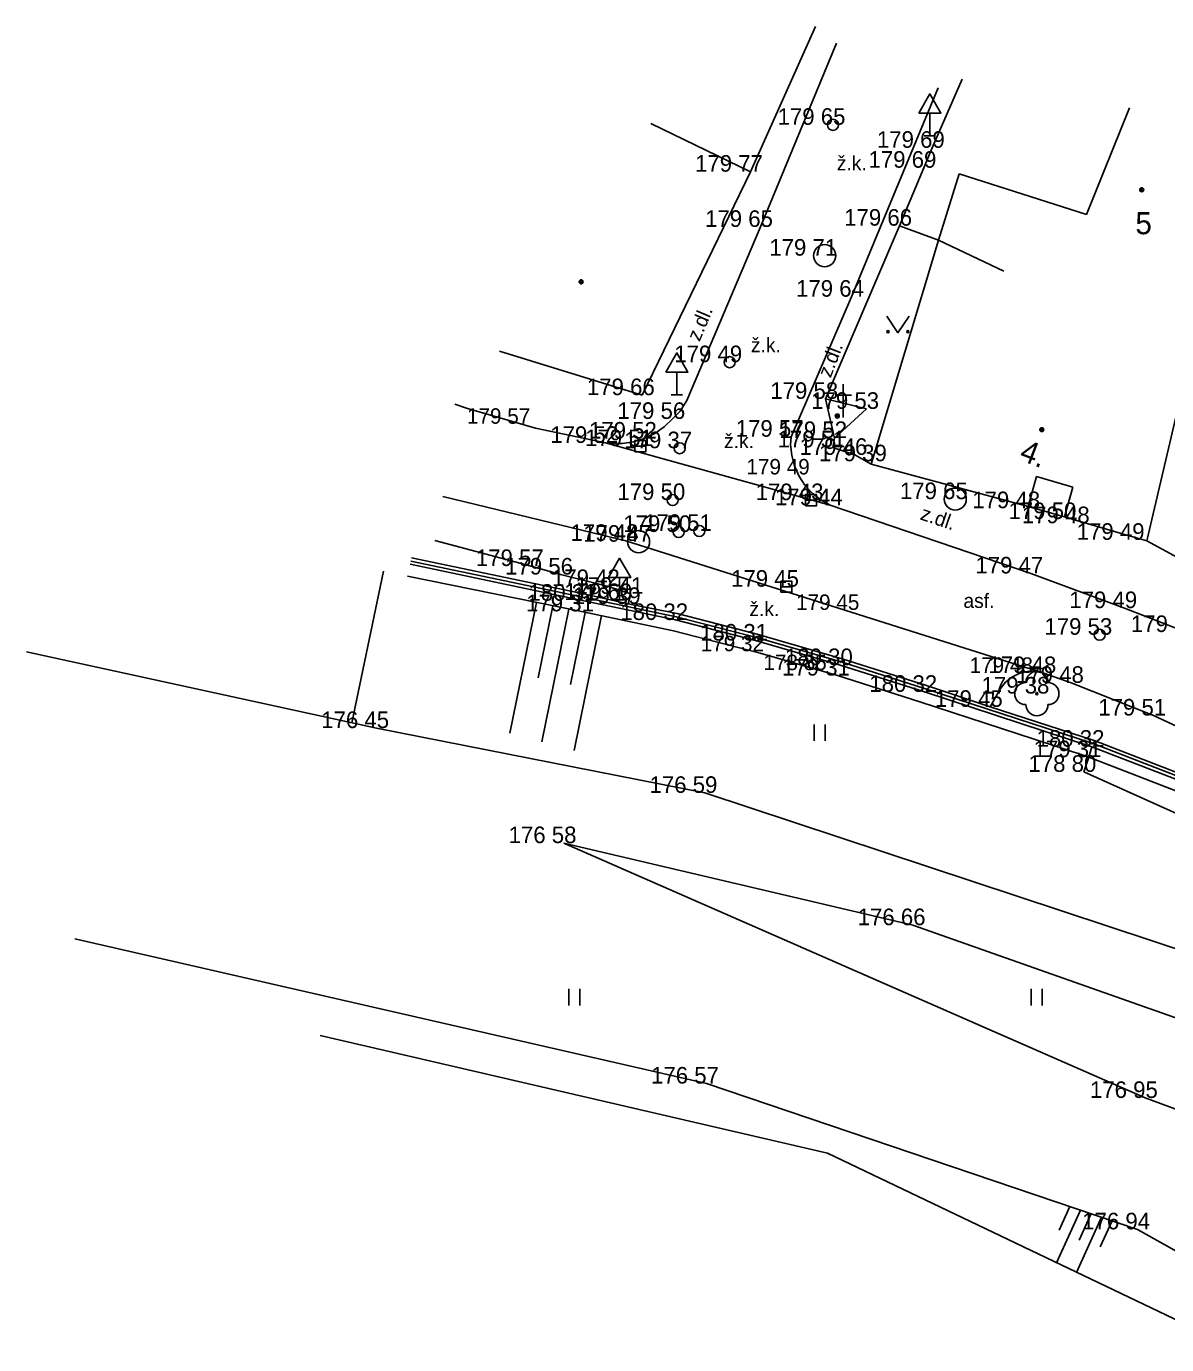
# Model space of a CAD drawing. Extents: x -537755 to -537431, y -1180722 to -1180510.
# Drawn here: x -537754.9 to -537703.4, y -1180569.1 to -1180509.5 of the extents above; entities that cross this region are included whole.
import ezdxf

# ---------------------------------------------------------------- set-up
doc = ezdxf.new("R2010")
doc.units = 0
for name, color, linetype in [('Vrstva 1', 7, 'Continuous'), ('Vrstva 10', 7, 'Continuous'), ('Vrstva 11', 7, 'Continuous'), ('Vrstva 14', 7, 'Continuous'), ('Vrstva 15', 7, 'Continuous'), ('Vrstva 22', 7, 'Continuous'), ('Vrstva 27', 7, 'Continuous'), ('Vrstva 28', 7, 'Continuous'), ('Vrstva 3', 7, 'Continuous'), ('Vrstva 31', 7, 'Continuous'), ('Vrstva 34', 7, 'Continuous'), ('Vrstva 36', 7, 'Continuous'), ('Vrstva 39', 7, 'Continuous'), ('Vrstva 40', 7, 'Continuous'), ('Vrstva 41', 7, 'Continuous'), ('Vrstva 47', 7, 'Continuous'), ('Vrstva 5', 7, 'Continuous'), ('Vrstva 6', 7, 'Continuous'), ('Vrstva 7', 7, 'Continuous'), ('Vrstva 8', 7, 'Continuous'), ('Vrstva 9', 7, 'Continuous')]:
    doc.layers.add(name, color=color, linetype=linetype)

msp = doc.modelspace()

# ---------------------------------------------------------------- linework, layer by layer
at = {"layer": 'Vrstva 1'}
for p, q in [((-537718.52, -1180514.03), (-537718.52, -1180514.03)), ((-537718.49, -1180513.98), (-537718.49, -1180513.98)), ((-537718.434, -1180514.114), (-537718.434, -1180514.114)), ((-537714, -1180515.02), (-537714, -1180515.02)), ((-537714.38, -1180515.92), (-537714.38, -1180515.92)), ((-537722.22, -1180516.1), (-537722.22, -1180516.1)), ((-537720.86, -1180516.44), (-537720.86, -1180516.44)), ((-537721.769, -1180518.596), (-537721.769, -1180518.596)), ((-537715.48, -1180518.54), (-537715.48, -1180518.54)), ((-537718.865, -1180519.895), (-537718.865, -1180519.895)), ((-537717.656, -1180521.751), (-537717.656, -1180521.751)), ((-537723.16, -1180524.71), (-537723.16, -1180524.71)), ((-537727.14, -1180526.11), (-537727.14, -1180526.11)), ((-537727.11, -1180526.2), (-537727.11, -1180526.2)), ((-537727.04, -1180526.19), (-537727.04, -1180526.19)), ((-537727.11, -1180526.24), (-537727.11, -1180526.24)), ((-537725.093, -1180526.449), (-537725.093, -1180526.449)), ((-537718.82, -1180526.37), (-537718.82, -1180526.37)), ((-537718.64, -1180526.57), (-537718.64, -1180526.57)), ((-537725.734, -1180527.276), (-537725.734, -1180527.276)), ((-537716.97, -1180526.82), (-537716.97, -1180526.82)), ((-537732.701, -1180527.495), (-537732.701, -1180527.495)), ((-537726.117, -1180527.687), (-537726.117, -1180527.687)), ((-537720.248, -1180527.828), (-537720.248, -1180527.828)), ((-537720.07, -1180527.44), (-537720.07, -1180527.44)), ((-537728.765, -1180528.361), (-537728.765, -1180528.361)), ((-537728.157, -1180528.553), (-537728.157, -1180528.553)), ((-537727.195, -1180528.506), (-537727.195, -1180528.506)), ((-537727.176, -1180528.6), (-537727.176, -1180528.6)), ((-537727.016, -1180528.165), (-537727.016, -1180528.165)), ((-537725.42, -1180528.6), (-537725.42, -1180528.6)), ((-537720.383, -1180528.081), (-537720.383, -1180528.081)), ((-537718.49, -1180528.56), (-537718.49, -1180528.56)), ((-537718.42, -1180528.14), (-537718.42, -1180528.14)), ((-537718.28, -1180528.08), (-537718.28, -1180528.08)), ((-537717.5, -1180528.9), (-537717.5, -1180528.9)), ((-537716.62, -1180529.19), (-537716.62, -1180529.19)), ((-537720.22, -1180529.54), (-537720.22, -1180529.54)), ((-537720.067, -1180529.785), (-537720.067, -1180529.785)), ((-537716.76, -1180529.32), (-537716.76, -1180529.32)), ((-537716.73, -1180529.27), (-537716.73, -1180529.27)), ((-537719.94, -1180529.88), (-537719.94, -1180529.88)), ((-537725.732, -1180530.939), (-537725.732, -1180530.939)), ((-537720.26, -1180530.83), (-537720.26, -1180530.83)), ((-537719.664, -1180530.389), (-537719.664, -1180530.389)), ((-537719.481, -1180530.947), (-537719.481, -1180530.947)), ((-537712.96, -1180530.901), (-537712.96, -1180530.901)), ((-537719.385, -1180530.998), (-537719.385, -1180530.998)), ((-537718.611, -1180531.177), (-537718.611, -1180531.177)), ((-537718.48, -1180531.24), (-537718.48, -1180531.24)), ((-537718.319, -1180531.314), (-537718.319, -1180531.314)), ((-537709.69, -1180531.31), (-537709.69, -1180531.31)), ((-537708.05, -1180531.8), (-537708.05, -1180531.8)), ((-537707.45, -1180531.99), (-537707.45, -1180531.99)), ((-537725.465, -1180532.386), (-537725.465, -1180532.386)), ((-537725.43, -1180532.33), (-537725.43, -1180532.33)), ((-537724.53, -1180532.38), (-537724.53, -1180532.38)), ((-537724.528, -1180532.338), (-537724.528, -1180532.338)), ((-537704.97, -1180532.74), (-537704.97, -1180532.74)), ((-537727.849, -1180532.79), (-537727.849, -1180532.79)), ((-537727.39, -1180532.82), (-537727.39, -1180532.82)), ((-537727.275, -1180532.826), (-537727.275, -1180532.826)), ((-537727.233, -1180532.863), (-537727.233, -1180532.863)), ((-537704.3, -1180532.78), (-537704.3, -1180532.78)), ((-537732.13, -1180533.925), (-537732.13, -1180533.925)), ((-537730.807, -1180534.309), (-537730.807, -1180534.309)), ((-537709.549, -1180534.261), (-537709.549, -1180534.261)), ((-537728.69, -1180534.83), (-537728.69, -1180534.83)), ((-537720.593, -1180534.859), (-537720.593, -1180534.859)), ((-537729.748, -1180535.494), (-537729.748, -1180535.494)), ((-537728.13, -1180535.46), (-537728.13, -1180535.46)), ((-537727.75, -1180535.64), (-537727.75, -1180535.64)), ((-537727.63, -1180535.18), (-537727.63, -1180535.18)), ((-537705.49, -1180535.64), (-537705.49, -1180535.64)), ((-537729.861, -1180535.974), (-537729.861, -1180535.974)), ((-537717.823, -1180535.909), (-537717.823, -1180535.909)), ((-537705.304, -1180535.827), (-537705.304, -1180535.827)), ((-537725.87, -1180536.37), (-537725.87, -1180536.37)), ((-537725.602, -1180536.364), (-537725.602, -1180536.364)), ((-537706.49, -1180536.9), (-537706.49, -1180536.9)), ((-537721.99, -1180537.295), (-537721.99, -1180537.295)), ((-537706.429, -1180537.032), (-537706.429, -1180537.032)), ((-537722.135, -1180537.775), (-537722.135, -1180537.775)), ((-537719.301, -1180538.63), (-537719.301, -1180538.63)), ((-537718.45, -1180538.38), (-537718.45, -1180538.38)), ((-537718.159, -1180538.404), (-537718.159, -1180538.404)), ((-537718.289, -1180538.876), (-537718.289, -1180538.876)), ((-537709.978, -1180538.754), (-537709.978, -1180538.754)), ((-537708.96, -1180538.764), (-537708.96, -1180538.764)), ((-537707.713, -1180539.205), (-537707.713, -1180539.205)), ((-537714.344, -1180539.612), (-537714.344, -1180539.612)), ((-537709.27, -1180539.69), (-537709.27, -1180539.69)), ((-537711.38, -1180540.29), (-537711.38, -1180540.29)), ((-537703.993, -1180540.684), (-537703.993, -1180540.684)), ((-537739.12, -1180541.25), (-537739.12, -1180541.25)), ((-537706.82, -1180542.13), (-537706.82, -1180542.13)), ((-537706.782, -1180542.092), (-537706.782, -1180542.092)), ((-537706.917, -1180542.563), (-537706.917, -1180542.563)), ((-537707.15, -1180543.23), (-537707.15, -1180543.23)), ((-537724.28, -1180544.18), (-537724.28, -1180544.18)), ((-537730.65, -1180546.45), (-537730.65, -1180546.45)), ((-537714.87, -1180550.16), (-537714.87, -1180550.16)), ((-537724.21, -1180557.32), (-537724.21, -1180557.32)), ((-537704.37, -1180557.97), (-537704.37, -1180557.97)), ((-537704.72, -1180563.91), (-537704.72, -1180563.91))]:
    msp.add_line(p, q, dxfattribs=at)
at = {"layer": 'Vrstva 10'}
for p, q in [((-537718.33, -1180510.282), (-537721.769, -1180518.596)), ((-537721.769, -1180518.596), (-537725.093, -1180526.449)), ((-537720.383, -1180528.081), (-537717.656, -1180521.751)), ((-537728.765, -1180528.361), (-537718.611, -1180531.177)), ((-537736.128, -1180530.783), (-537727.849, -1180532.79)), ((-537709.549, -1180534.261), (-537718.611, -1180531.177)), ((-537708.96, -1180538.764), (-537727.849, -1180532.79)), ((-537703.993, -1180540.684), (-537697.619, -1180543.667))]:
    msp.add_line(p, q, dxfattribs=at)
for points in [[(-537716.643, -1180519.316), (-537713.728, -1180512.314)], [(-537717.656, -1180521.751), (-537716.643, -1180519.316)], [(-537728.765, -1180528.361), (-537731.935, -1180527.693), (-537735.048, -1180526.793), (-537735.582, -1180526.613)], [(-537725.093, -1180526.449), (-537725.395, -1180526.93), (-537725.734, -1180527.276)], [(-537725.734, -1180527.276), (-537726.111, -1180527.635), (-537726.538, -1180527.932), (-537727.016, -1180528.165), (-537727.502, -1180528.315), (-537728.017, -1180528.391), (-537728.538, -1180528.388), (-537728.765, -1180528.361)], [(-537718.611, -1180531.177), (-537719.042, -1180530.937), (-537719.429, -1180530.631), (-537719.762, -1180530.266), (-537720.032, -1180529.853), (-537720.231, -1180529.401), (-537720.354, -1180528.923), (-537720.4, -1180528.432), (-537720.383, -1180528.081)], [(-537736.491, -1180532.767), (-537732.13, -1180533.925), (-537730.807, -1180534.309), (-537728.69, -1180534.83)], [(-537702.519, -1180536.908), (-537705.304, -1180535.827), (-537709.549, -1180534.261)], [(-537728.69, -1180534.83), (-537727.63, -1180535.18), (-537727.75, -1180535.64)], [(-537711.38, -1180540.29), (-537710.92, -1180539.462), (-537710.687, -1180539.176), (-537710.398, -1180538.946), (-537710.067, -1180538.783), (-537709.708, -1180538.696), (-537709.339, -1180538.688), (-537708.96, -1180538.764)], [(-537708.96, -1180538.764), (-537707.713, -1180539.205), (-537703.993, -1180540.684)]]:
    msp.add_lwpolyline(points, dxfattribs=at)
at = {"layer": 'Vrstva 11'}
msp.add_line((-537715.48, -1180518.54), (-537718.82, -1180526.37), dxfattribs=at)
msp.add_lwpolyline([(-537718.42, -1180528.14), (-537718.49, -1180528.56), (-537717.5, -1180528.9), (-537716.76, -1180529.32)], dxfattribs=at)
at = {"layer": 'Vrstva 14'}
for p, q in [((-537754.95, -1180537.81), (-537739.12, -1180541.25)), ((-537739.12, -1180541.25), (-537724.28, -1180544.18)), ((-537700.77, -1180546.1), (-537707.15, -1180543.23)), ((-537724.28, -1180544.18), (-537700.48, -1180552.05)), ((-537730.65, -1180546.45), (-537714.87, -1180550.16)), ((-537730.65, -1180546.45), (-537704.37, -1180557.97)), ((-537714.87, -1180550.16), (-537694.25, -1180557.43)), ((-537724.21, -1180557.32), (-537752.76, -1180550.78)), ((-537741.67, -1180555.14), (-537718.74, -1180560.47)), ((-537704.72, -1180563.91), (-537724.21, -1180557.32)), ((-537704.37, -1180557.97), (-537687.94, -1180563.99)), ((-537718.74, -1180560.47), (-537699.95, -1180569.45)), ((-537683.35, -1180575.9), (-537704.72, -1180563.91))]:
    msp.add_line(p, q, dxfattribs=at)
msp.add_lwpolyline([(-537707.15, -1180543.23), (-537706.917, -1180542.563), (-537706.782, -1180542.092)], dxfattribs=at)
at = {"layer": 'Vrstva 15'}
for p, q in [((-537740.233, -1180541.008), (-537738.809, -1180534.154)), ((-537733.094, -1180541.483), (-537731.89, -1180535.57)), ((-537731.82, -1180538.986), (-537731.155, -1180535.719)), ((-537731.643, -1180541.873), (-537730.42, -1180535.869)), ((-537730.35, -1180539.285), (-537729.685, -1180536.019)), ((-537730.192, -1180542.264), (-537728.95, -1180536.168)), ((-537707.295, -1180563.039), (-537708.375, -1180565.423)), ((-537707.773, -1180562.878), (-537708.258, -1180563.952)), ((-537706.345, -1180563.361), (-537707.473, -1180565.855)), ((-537706.82, -1180563.2), (-537707.365, -1180564.403)), ((-537705.868, -1180563.522), (-537706.404, -1180564.706))]:
    msp.add_line(p, q, dxfattribs=at)
at = {"layer": 'Vrstva 22'}
msp.add_circle((-537709.27, -1180539.69), 0.05, dxfattribs=at)
for centre, start, end in [((-537709.27, -1180539.19), 0, 180), ((-537709.77, -1180539.69), 90, 270), ((-537708.77, -1180539.69), 270, 90), ((-537709.27, -1180540.19), 180, 0)]:
    msp.add_arc(centre, 0.5, start, end, dxfattribs=at)
at = {"layer": 'Vrstva 27'}
for p, q in [((-537727.445, -1180528.506), (-537726.945, -1180528.506)), ((-537719.731, -1180530.947), (-537719.231, -1180530.947)), ((-537720.843, -1180534.859), (-537720.343, -1180534.859))]:
    msp.add_line(p, q, dxfattribs=at)
for points in [[(-537727.445, -1180528.756), (-537726.945, -1180528.756), (-537726.945, -1180528.256), (-537727.445, -1180528.256)], [(-537719.731, -1180531.197), (-537719.231, -1180531.197), (-537719.231, -1180530.697), (-537719.731, -1180530.697)], [(-537720.843, -1180535.109), (-537720.343, -1180535.109), (-537720.343, -1180534.609), (-537720.843, -1180534.609)]]:
    msp.add_lwpolyline(points, close=True, dxfattribs=at)
for centre in [(-537718.865, -1180519.895), (-537712.96, -1180530.901), (-537727.275, -1180532.826)]:
    msp.add_circle(centre, 0.5, dxfattribs=at)
at = {"layer": 'Vrstva 28'}
for centre in [(-537718.49, -1180513.98), (-537723.16, -1180524.71), (-537725.732, -1180530.939), (-537725.465, -1180532.386), (-537724.528, -1180532.338), (-537706.429, -1180537.032)]:
    msp.add_circle(centre, 0.25, dxfattribs=at)
at = {"layer": 'Vrstva 31'}
msp.add_circle((-537725.42, -1180528.6), 0.25, dxfattribs=at)
at = {"layer": 'Vrstva 34'}
for p, q in [((-537714.11, -1180513.453), (-537714.11, -1180514.471)), ((-537714.36, -1180514.471), (-537713.86, -1180514.471)), ((-537725.544, -1180525.161), (-537725.544, -1180526.179)), ((-537725.794, -1180526.179), (-537725.294, -1180526.179)), ((-537728.13, -1180534.444), (-537728.13, -1180535.46)), ((-537728.38, -1180535.46), (-537727.88, -1180535.46))]:
    msp.add_line(p, q, dxfattribs=at)
for points in [[(-537714.61, -1180513.453), (-537713.61, -1180513.453), (-537714.11, -1180512.587)], [(-537726.044, -1180525.161), (-537725.044, -1180525.161), (-537725.544, -1180524.295)], [(-537728.63, -1180534.444), (-537727.63, -1180534.444), (-537728.13, -1180533.576)]]:
    msp.add_lwpolyline(points, close=True, dxfattribs=at)
at = {"layer": 'Vrstva 36'}
for p, q in [((-537719.339, -1180541.831), (-537719.339, -1180541.081)), ((-537718.839, -1180541.831), (-537718.839, -1180541.081)), ((-537730.435, -1180553.785), (-537730.435, -1180553.035)), ((-537729.935, -1180553.785), (-537729.935, -1180553.035)), ((-537709.523, -1180553.785), (-537709.523, -1180553.035)), ((-537709.023, -1180553.785), (-537709.023, -1180553.035))]:
    msp.add_line(p, q, dxfattribs=at)
msp.add_lwpolyline([(-537716.05, -1180522.631), (-537715.55, -1180523.381), (-537715.05, -1180522.631)], dxfattribs=at)
for centre in [(-537716, -1180523.331), (-537715.101, -1180523.331)]:
    msp.add_circle(centre, 0.05, dxfattribs=at)
at = {"layer": 'Vrstva 39'}
for centre, radius in [((-537704.531, -1180516.916), 0.09), ((-537704.531, -1180516.916), 0.0398), ((-537729.871, -1180521.078), 0.09), ((-537729.871, -1180521.078), 0.0398), ((-537718.293, -1180527.144), 0.09), ((-537718.293, -1180527.144), 0.0398), ((-537709.049, -1180527.761), 0.09), ((-537709.049, -1180527.761), 0.0398)]:
    msp.add_circle(centre, radius, dxfattribs=at)
at = {"layer": 'Vrstva 41'}
for p, q in [((-537718.395, -1180526.207), (-537717.645, -1180526.207)), ((-537718.02, -1180527.207), (-537718.02, -1180525.707))]:
    msp.add_line(p, q, dxfattribs=at)
at = {"layer": 'Vrstva 5'}
for p, q in [((-537722.22, -1180516.1), (-537719.27, -1180509.53)), ((-537726.72, -1180513.921), (-537722.22, -1180516.1)), ((-537727.11, -1180526.2), (-537722.22, -1180516.1)), ((-537713.72, -1180519.19), (-537712.78, -1180516.19)), ((-537712.78, -1180516.19), (-537707.023, -1180518.032)), ((-537713.72, -1180519.19), (-537716.76, -1180529.32)), ((-537710.766, -1180520.598), (-537713.72, -1180519.19)), ((-537704.3, -1180532.78), (-537701.72, -1180521.76)), ((-537728.09, -1180525.897), (-537733.561, -1180524.209)), ((-537716.97, -1180526.82), (-537718.82, -1180526.37)), ((-537718.82, -1180526.37), (-537718.42, -1180528.14)), ((-537718.42, -1180528.14), (-537716.97, -1180526.82)), ((-537716.76, -1180529.32), (-537709.668, -1180531.229)), ((-537709.668, -1180531.229), (-537709.282, -1180529.883)), ((-537709.282, -1180529.883), (-537707.637, -1180530.354)), ((-537707.637, -1180530.354), (-537708.022, -1180531.7)), ((-537709.668, -1180531.229), (-537708.022, -1180531.7)), ((-537708.022, -1180531.7), (-537707.42, -1180531.883)), ((-537704.932, -1180532.605), (-537704.3, -1180532.78)), ((-537694.81, -1180537.96), (-537704.3, -1180532.78))]:
    msp.add_line(p, q, dxfattribs=at)
for points in [[(-537707.023, -1180518.032), (-537705.076, -1180513.21)], [(-537727.11, -1180526.2), (-537728.09, -1180525.897)]]:
    msp.add_lwpolyline(points, dxfattribs=at)
at = {"layer": 'Vrstva 6'}
msp.add_line((-537707.42, -1180531.883), (-537704.932, -1180532.605), dxfattribs=at)
at = {"layer": 'Vrstva 7'}
for p, q in [((-537714, -1180515.02), (-537712.64, -1180511.91)), ((-537715.48, -1180518.54), (-537714.38, -1180515.92)), ((-537713.72, -1180519.19), (-537715.48, -1180518.54)), ((-537729.748, -1180535.494), (-537737.605, -1180533.848)), ((-537729.686, -1180535.2), (-537737.543, -1180533.554)), ((-537729.861, -1180535.974), (-537737.718, -1180534.383)), ((-537706.782, -1180542.092), (-537714.344, -1180539.612)), ((-537707.182, -1180542.476), (-537714.563, -1180540.056)), ((-537699.762, -1180544.81), (-537706.782, -1180542.092)), ((-537699.647, -1180544.533), (-537706.681, -1180541.809)), ((-537706.917, -1180542.563), (-537707.182, -1180542.476)), ((-537699.969, -1180545.27), (-537706.917, -1180542.563))]:
    msp.add_line(p, q, dxfattribs=at)
for points in [[(-537721.99, -1180537.295), (-537725.602, -1180536.364), (-537729.748, -1180535.494)], [(-537727.75, -1180535.64), (-537729.686, -1180535.2)], [(-537721.911, -1180537.006), (-537725.534, -1180536.072), (-537727.75, -1180535.64)], [(-537721.773, -1180537.868), (-537725.7, -1180536.856), (-537729.861, -1180535.974)], [(-537714.344, -1180539.612), (-537718.159, -1180538.404), (-537721.99, -1180537.295)], [(-537714.252, -1180539.326), (-537718.072, -1180538.117), (-537721.911, -1180537.006)], [(-537714.563, -1180540.056), (-537718.289, -1180538.876), (-537721.773, -1180537.868)], [(-537706.681, -1180541.809), (-537711.38, -1180540.29), (-537714.252, -1180539.326)]]:
    msp.add_lwpolyline(points, dxfattribs=at)
at = {"layer": 'Vrstva 8'}
msp.add_line((-537714, -1180515.02), (-537714.38, -1180515.92), dxfattribs=at)
at = {"layer": 'Vrstva 9'}
for p, q in [((-537729.717, -1180535.347), (-537737.574, -1180533.701)), ((-537706.732, -1180541.951), (-537714.298, -1180539.469)), ((-537699.704, -1180544.671), (-537706.732, -1180541.951))]:
    msp.add_line(p, q, dxfattribs=at)
for points in [[(-537721.95, -1180537.15), (-537725.568, -1180536.218), (-537729.717, -1180535.347)], [(-537714.298, -1180539.469), (-537718.115, -1180538.26), (-537721.95, -1180537.15)]]:
    msp.add_lwpolyline(points, dxfattribs=at)

# ---------------------------------------------------------------- texts
at = {"layer": 'Vrstva 3'}
for s, height, p in [('179 65 ', 0.75, (-537720.99, -1180513.98)), ('179 69 ', 0.75, (-537716.5, -1180515.02)), ('179 77 ', 0.75, (-537724.72, -1180516.1)), ('179 69 ', 0.75, (-537716.88, -1180515.92)), ('179 65 ', 0.75, (-537724.269, -1180518.596)), ('179 66 ', 0.75, (-537717.98, -1180518.54)), ('179 71 ', 0.75, (-537721.365, -1180519.895)), ('179 64 ', 0.75, (-537720.156, -1180521.751)), ('179 49 ', 0.75, (-537725.66, -1180524.71)), ('179 66 ', 0.75, (-537729.61, -1180526.2)), ('179 58 ', 0.75, (-537721.32, -1180526.37)), ('179 53 ', 0.75, (-537719.47, -1180526.82)), ('179 57 ', 0.7, (-537735.034, -1180527.495)), ('179 56 ', 0.75, (-537728.234, -1180527.276)), ('179 52 ', 0.75, (-537729.516, -1180528.165)), ('179 57 ', 0.75, (-537722.883, -1180528.081)), ('179 52 ', 0.75, (-537720.92, -1180528.14)), ('179 52 ', 0.75, (-537731.265, -1180528.361)), ('179 51 ', 0.75, (-537729.695, -1180528.506)), ('179 37 ', 0.75, (-537727.92, -1180528.6)), ('179 51 ', 0.75, (-537720.99, -1180528.56)), ('179 46 ', 0.75, (-537720, -1180528.9)), ('179 39 ', 0.75, (-537719.12, -1180529.19)), ('179 49 ', 0.7, (-537722.4, -1180529.785)), ('179 50 ', 0.75, (-537728.232, -1180530.939)), ('179 43 ', 0.75, (-537721.981, -1180530.947)), ('179 65 ', 0.75, (-537715.46, -1180530.901)), ('179 44 ', 0.75, (-537721.111, -1180531.177)), ('179 48 ', 0.75, (-537712.19, -1180531.31)), ('179 51 ', 0.75, (-537727.028, -1180532.338)), ('179 50 ', 0.75, (-537710.55, -1180531.8)), ('179 48 ', 0.75, (-537709.95, -1180531.99)), ('179 48 ', 0.75, (-537730.349, -1180532.79)), ('179 47 ', 0.75, (-537729.775, -1180532.826)), ('179 50 ', 0.75, (-537727.965, -1180532.386)), ('179 49 ', 0.75, (-537707.47, -1180532.74)), ('179 57 ', 0.75, (-537734.63, -1180533.925)), ('179 56 ', 0.75, (-537733.307, -1180534.309)), ('179 47 ', 0.75, (-537712.049, -1180534.261)), ('179 42 ', 0.75, (-537731.19, -1180534.83)), ('179 41 ', 0.75, (-537730.13, -1180535.18)), ('179 45 ', 0.75, (-537723.093, -1180534.859)), ('180 31 ', 0.75, (-537732.248, -1180535.494)), ('179 60 ', 0.75, (-537730.63, -1180535.46)), ('179 39 ', 0.75, (-537730.25, -1180535.64)), ('179 49 ', 0.75, (-537707.804, -1180535.827)), ('179 31 ', 0.75, (-537732.361, -1180535.974)), ('180 32 ', 0.75, (-537728.102, -1180536.364)), ('179 45 ', 0.7, (-537720.156, -1180535.909)), ('179 53 ', 0.75, (-537708.929, -1180537.032)), ('179 51 ', 0.75, (-537705.019, -1180536.908)), ('180 31 ', 0.75, (-537724.49, -1180537.295)), ('179 32 ', 0.7, (-537724.468, -1180537.775)), ('178 85 ', 0.7, (-537721.634, -1180538.63)), ('179 31 ', 0.75, (-537720.789, -1180538.876)), ('180 30 ', 0.75, (-537720.659, -1180538.404)), ('179 48 ', 0.7, (-537712.311, -1180538.754)), ('179 48 ', 0.75, (-537711.46, -1180538.764)), ('179 48 ', 0.75, (-537710.213, -1180539.205)), ('180 32 ', 0.75, (-537716.844, -1180539.612)), ('179 38 ', 0.75, (-537711.77, -1180539.69)), ('179 45 ', 0.75, (-537713.88, -1180540.29)), ('176 45 ', 0.75, (-537741.62, -1180541.25)), ('179 51 ', 0.75, (-537706.493, -1180540.684)), ('180 32 ', 0.75, (-537709.282, -1180542.092)), ('179 31 ', 0.75, (-537709.417, -1180542.563)), ('178 80 ', 0.75, (-537709.65, -1180543.23)), ('176 59 ', 0.75, (-537726.78, -1180544.18)), ('176 58 ', 0.75, (-537733.15, -1180546.45)), ('176 66 ', 0.75, (-537717.37, -1180550.16)), ('176 57 ', 0.75, (-537726.71, -1180557.32)), ('176 95 ', 0.75, (-537706.87, -1180557.97)), ('176 94 ', 0.75, (-537707.22, -1180563.91))]:
    msp.add_text(s, height=height, dxfattribs=at).set_placement(p)
at = {"layer": 'Vrstva 40'}
for s, p in [('ž.k.', (-537718.312, -1180516.037)), ('ž.k.', (-537722.196, -1180524.26)), ('ž.k.', (-537723.411, -1180528.596)), ('asf.', (-537712.589, -1180535.819)), ('ž.k.', (-537722.266, -1180536.188))]:
    msp.add_text(s, height=0.65, dxfattribs=at).set_placement(p)
for rotation, p in [(67.05814, (-537724.519, -1180523.811)), (68.83479, (-537718.593, -1180525.451)), (341.20542, (-537714.587, -1180531.807))]:
    msp.add_text('z.dl.', height=0.65, rotation=rotation, dxfattribs=at).set_placement(p)
at = {"layer": 'Vrstva 47'}
msp.add_text('5', height=1, dxfattribs=at).set_placement((-537704.815, -1180518.926))
msp.add_text('4.', height=1, rotation=338.97888, dxfattribs=at).set_placement((-537710.11, -1180529.111))

doc.saveas('drawing.dxf')
